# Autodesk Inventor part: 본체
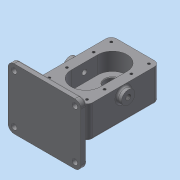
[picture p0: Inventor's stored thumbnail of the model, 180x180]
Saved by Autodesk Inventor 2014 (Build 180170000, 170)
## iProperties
Created: 2026-10
Part Number: 본체
Material: 일반
Document SubType Name: Modeling
Designer: dg
Density: 1 g/cm^3
Appearance: 기본값
Author: dg
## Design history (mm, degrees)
sketch "스케치1"
  geometry: L1 (-40, 60)-(40, 60); L2 (40, 60)-(40, -60); L3 (40, -60)-(-40, -60); L4 (-40, -60)-(-40, 60); 3 further points
  constraints: 8 end point, 2 midpoint, 2 parallel, 1 horizontal, 1 horizontal alignment, 1 perpendicular, 1 vertical alignment
  dimensions: "d0" = 80 distance of L1.start L1.end; "d1" = 120 distance of L1.end L2.end
extrude "돌출1" new body sketch "스케치1" stored distance "d2" = 53; taper "d3" = 0 deg
sketch "스케치2"
  geometry: L1 (-40, 60)-(-40, -60) reference; L2 (0, 22)-(0, -22); L3 (-24, 22)-(-24, -22); L4 (24, -22)-(24, 22); A1 r 24 centre (0, 22) between (24, 22) and (-24, 22); A2 r 24 centre (0, -22) between (-24, -22) and (24, -22); 2 further points
  constraints: 8 end point, 4 point on circle, 4 tangent, 2 centre point, 2 parallel, 1 coincident, 1 midpoint
  dimensions: "d4" = 48 distance between parallel lines of L4 L3; "d5" = 44 distance of L4.start L4.end
extrude "돌출2" cut sketch "스케치2" distance "d6" = 29; taper "d7" = 0 deg
node "작업 평면1"
sketch "스케치3"
  geometry: L1 (-20, 70)-(100, 70); L2 (100, 70)-(100, -30); L3 (100, -30)-(-20, -30); L4 (-20, -30)-(-20, 70); L5 (0, 53)-(80, 53) reference; L6 (0, 53)-(0, 0) reference; L7 (80, 0)-(0, 0) reference; L8 (80, 0)-(80, 53) reference; L9 (0, 53)-(80, 53) reference; 1 further point
  constraints: 8 end point, 2 parallel, 1 horizontal, 1 perpendicular
  dimensions: "d9" = 100 distance of L3.end L1.start; "d10" = 120 distance of L2.end L3.end; "d25" = 17 distance between parallel lines of L1 L5; "d26" = 20 distance between parallel lines of L2 L8
extrude "돌출3" join sketch "스케치3" distance "d11" = 10; taper "d12" = 0 deg
sketch "스케치4"
  geometry: L1 (-60, 26.5)-(-60, -26.5) reference; L2 (-80, -43.5)-(-80, 56.5) reference; L3 (-57, 13.221)-(-80, 26.5); L4 (-57, -13.221)-(-80, -26.5); L5 (-57, 13.221)-(-57, -13.221); L6 (-80, 26.5)-(-80, -26.5); 3 further points
  constraints: 8 end point, 2 horizontal alignment, 2 midpoint, 2 point on line, 1 collinear, 1 parallel
  dimensions: "d13" = 53 distance of L4.end L3.end; "d14" = 60 deg angle of L2 L3; "d15" = 3 distance between parallel lines of L5 L1
extrude "돌출4" join sketch "스케치4" stored distance "d16" = 48; taper "d17" = 0 deg
sketch "스케치5"
  geometry: A1 r 24 centre (0, -22) between (-24, -22) and (24, -22) reference; A2 r 24 centre (0, 22) between (24, 22) and (-24, 22) reference; 1 further point
hole "구멍1" sketch "스케치5" at (0, 22), (0, -22) diameter "d18" = 25; stored, may be unused: countersink angle "d22" = 90 deg, drill point angle "d24" = 0 deg; dims "d19" = 6, "d20" = 4, "d21" = 2, "d23" = 15
sketch "스케치6"
  geometry: C1 r 12.5 at (0, 22) reference; C2 r 19 at (0, 22); 1 further point
  constraints: 1 centre point, 1 coincident
  dimensions: "d27" = 38 diameter of C2
extrude "돌출5" join sketch "스케치6" distance "d28" = 17; taper "d29" = 0 deg
sketch "스케치7"
  geometry: C1 r 19 at (0, 0) reference; 1 further point
hole "구멍2" sketch "스케치7" at (0, 0) diameter "d30" = 17; stored, may be unused: countersink angle "d34" = 90 deg, drill point angle "d36" = 0 deg; dims "d31" = 6, "d32" = 28, "d33" = 7.3, "d35" = 15
sketch "스케치8"
  geometry: L1 (0, 0)-(0, 120) reference; L2 (70, -30)-(-30, -30) reference; C1 r 11 at (14, 60); 1 further point
  constraints: 1 centre point
  dimensions: "d37" = 14 distance from line of L1 C1.centre; "d38" = 22 diameter of C1; "d39" = 90 distance from line of L2 C1.centre
extrude "돌출6" join sketch "스케치8" distance "d40" = 8; taper "d41" = 0 deg
sketch "스케치9"
  geometry: C1 r 11 at (-14, 60) reference; C2 r 11 at (-14, 60); 1 further point
  constraints: 1 centre point, 1 coincident, 1 concentric
extrude "돌출7" join sketch "스케치9" distance "d42" = 8; taper "d43" = 0 deg
hole "구멍3" diameter "d46" = 8; stored, may be unused: countersink angle "d52" = 90 deg, drill point angle "d54" = 118 deg; dims "d44" = 10, "d45" = 10, "d47" = 9, "d48" = 0.62479, "d49" = 7.985, "d50" = 28, "d51" = 7.3, "d53" = 30
hole "구멍4" diameter "d57" = 8; stored, may be unused: countersink angle "d63" = 90 deg, drill point angle "d65" = 118 deg; dims "d55" = 10, "d56" = 10, "d58" = 9, "d59" = 0.62479, "d60" = 7.985, "d61" = 28, "d62" = 7.3, "d64" = 30
sketch "스케치10"
  geometry: A1 r 24 centre (0, -22) between (-24, -22) and (24, -22) reference; A2 r 24 centre (0, 22) between (24, 22) and (-24, 22) reference; 9 further points
  constraints: 6 horizontal alignment, 6 vertical alignment
  dimensions: "d66" = 62 distance of point (31, 51) point (-31, 51); "d67" = 29 distance of point (-31, 22) point (-31, 51); "d68" = 29 distance of point (-31, -51) point (-31, -22); "d69" = 31 horizontal distance of A1.centre point (-31, -51)
hole "구멍5" sketch "스케치10" at (-31, 51), (-31, 22), (31, 22), (31, 51), (31, -22), (-31, -22), (-31, -51), (31, -51) diameter "d70" = 4.134; stored, may be unused: countersink angle "d74" = 90 deg, drill point angle "d76" = 118 deg; dims "d71" = 10, "d72" = 28, "d73" = 7.3, "d75" = 12
fillet "모깎기1" dims "d77" = 10
sketch "스케치11"
  geometry: A1 r 10 centre (-10, 60) between (-10, 70) and (-20, 60) reference; A2 r 10 centre (-10, -20) between (-20, -20) and (-10, -30) reference; A3 r 10 centre (90, -20) between (90, -30) and (100, -20) reference; A4 r 10 centre (90, 60) between (100, 60) and (90, 70) reference; 1 further point
hole "구멍6" sketch "스케치11" at (-10, 60), (-10, -20), (90, -20), (90, 60) diameter "d78" = 9; stored, may be unused: countersink angle "d82" = 82 deg, drill point angle "d84" = 0 deg; dims "d79" = 10, "d80" = 3.023, "d81" = 7.3, "d83" = 12
chamfer "모따기1" distance "d85" = 0.7; stored, may be unused: second distance "d86" = 2, angle "d87" = 30 deg
fillet "모깎기2" dims "d88" = 0.5
fillet "모깎기3" dims "d89" = 9
fillet "모깎기4" dims "d90" = 3
fillet "모깎기5" dims "d91" = 3
chamfer "모따기2" distance "d92" = 1; stored, may be unused: second distance "d93" = 2, angle "d94" = 30 deg
sketch "스케치12"
  geometry: L1 (-10, -30)-(90, -30) reference; 2 further points
  constraints: 1 vertical alignment, 1 other
  dimensions: "d95" = 10 distance from line of L1 point (40, -20)
feature "엠보싱1" sketch "스케치12" dims "d0" = 80, "d1" = 120, "d96" = 0.5, "d97" = 0
node "솔리드1"
node "투영된 루프1"
